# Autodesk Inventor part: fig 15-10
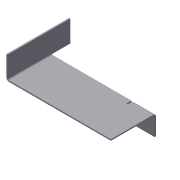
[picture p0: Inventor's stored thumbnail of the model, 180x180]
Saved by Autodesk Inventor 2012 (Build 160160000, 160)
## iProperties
Shininess: 77.0
Angle Display Precision: 2
Document Length Units: 11269
Document Angle Units: 11279
Document Time Units: 11290
Document Mass Units: 11283
Document Length Units Precision: 3
Document Angle Units Precision: 2
Created: 2002-04
Part Number: fig 15-10
Material: Aluminum-6061
Document SubType Name: Sheet Metal
Density: 1 g/cm^3
Sheet Metal Rule: Default
Density: 0.0
Volumn: 0.0
Area: 0.0
PropertySet Name: Model Information
Control State: 0
Master: False
Checked Out: False
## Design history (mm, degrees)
node "Face1"
  sketch "Sketch1"
    geometry: L1 (-49.559, 19.574)-(-49.559, -30.426); L2 (-49.559, -30.426)-(50.441, -30.426); L3 (50.441, -30.426)-(50.441, 19.574); L4 (50.441, 19.574)-(32.941, 19.574); L5 (32.941, 19.574)-(32.941, 4.574); L6 (32.941, 4.574)-(-32.059, 4.574); L7 (-32.059, 4.574)-(-32.059, 19.574); L8 (-32.059, 19.574)-(-49.559, 19.574)
    constraints: 16 end point, 6 parallel, 2 equal length, 1 perpendicular, 1 vertical
    dimensions: "d0" = 100 distance of L1.end L2.end; "d1" = 65 distance of L5.end L6.end; "d2" = 15 distance of L6.end L7.end; "d3" = 50 distance of L1.start L1.end
sketch "Sketch2"
  geometry: L1 (100, 0)-(0, 0) reference; L2 (17.5, 50)-(17.5, 35) reference; L3 (82.5, 50)-(82.5, 0)
  constraints: 2 end point, 1 parallel, 1 point on line
sketch "Sketch3"
  geometry: L1 (81.369, -50)-(0, -50) reference; L2 (17.5, 0)-(17.5, -50)
  constraints: 2 end point, 1 perpendicular, 1 point on line
feature "Fold2" sketch "Sketch3" dims "d8" = 1 (= BendRadius), "d9" = 90 deg, "d10" = 1 (= BendRadius), "d14" = 1 (= BendReliefWidth), "d15" = 0.5 (= BendReliefDepth), "d16" = 2 (= MinimumRemnant), "SeamGap" = 0.01, "Thickness" = 1
sketch "Sketch4"
  geometry: L1 (17.5, 0)-(17.5, -50) reference; L2 (-63.869, -15)-(0, -15) reference; L3 (0, -15)-(17.5, -15)
  constraints: 2 end point, 1 collinear, 1 point on line
feature "Fold3" sketch "Sketch4" dims "d11" = 1 (= BendRadius), "d12" = 90 deg, "d13" = 1 (= BendRadius), "d17" = 1, "d18" = 3, "d19" = 2 (= MinimumRemnant), "SeamGap" = 0.01, "Thickness" = 1
body "Solid1"
face "Plate1" dims "Thickness" = 1
other parameters: "BendRadius" = 1 (= Thickness), "BendReliefWidth" = 1 (= Thickness), "BendReliefDepth" = 0.5 (= 0.5 x Thickness), "CornerReliefSize" = 4 (= 4 x Thickness), "MinimumRemnant" = 2 (= 2 x Thickness), "TransitionRadius" = 1 (= BendRadius), "d4" = 1 (= BendRadius), "JacobiRadiusSize" = 1 (= Thickness), "GapSize" = 1 (= Thickness)
